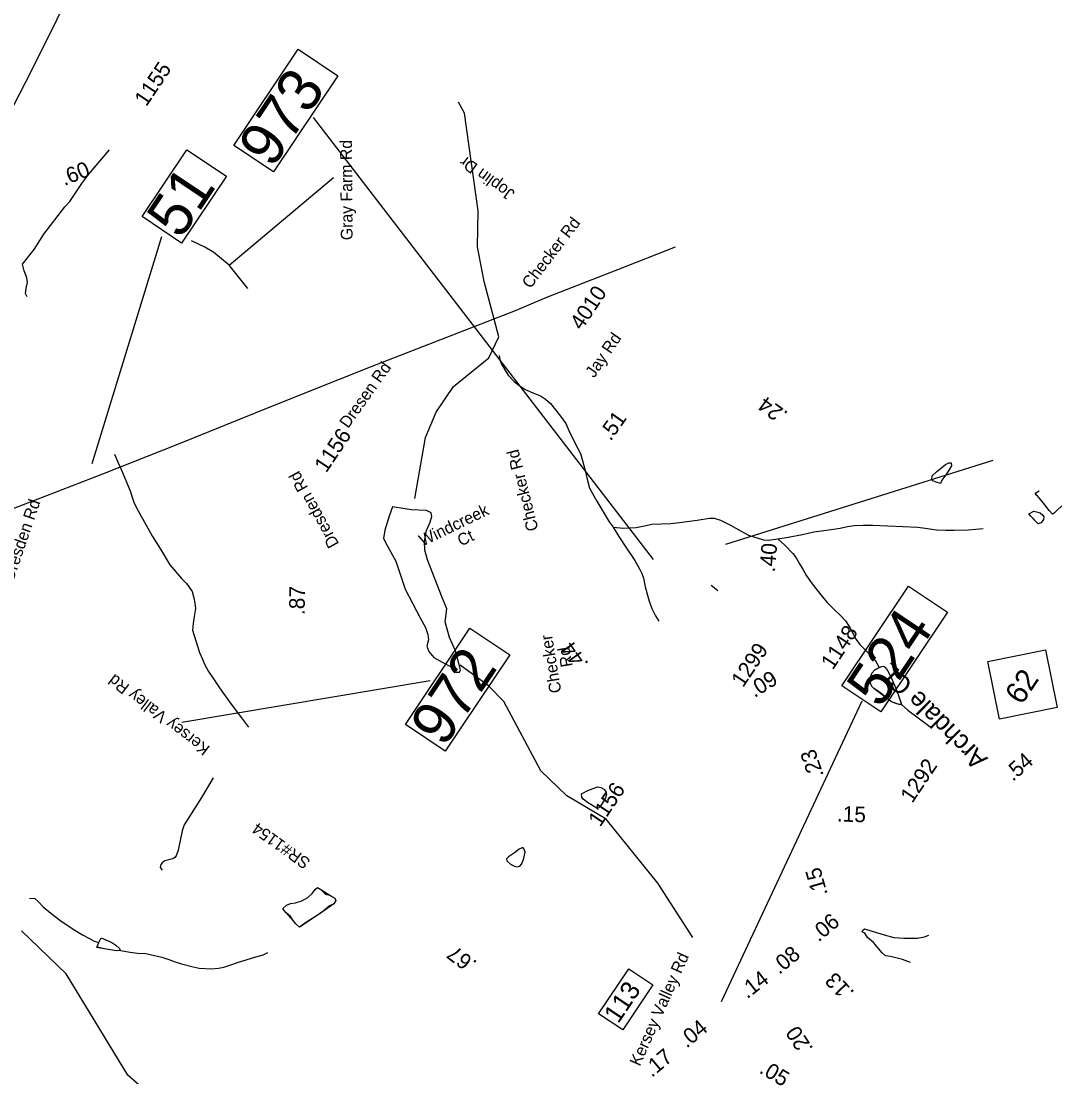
# Model space of a CAD drawing. Extents: x 1716282 to 1717158, y 799307 to 801078.
# Drawn here: x 1717037.3 to 1717158.4, y 800850 to 800972.8 of the extents above; entities that cross this region are included whole.
import ezdxf

# ---------------------------------------------------------------- set-up
doc = ezdxf.new("R2010")
doc.units = 0
for name, color, linetype in [('Exist Civil Demographics Community Label', 7, 'Continuous'), ('Exist Hydrographic Misc Water Feature', 7, 'Continuous'), ('Exist Hydrographic Pond Under 1500 Sq Ft', 7, 'Continuous'), ('Exist Road Non-System Type 51', 7, 'Continuous'), ('Exist Road Non-System Type 51 Label', 7, 'Continuous'), ('Exist Road Primary Interstate Interchange CELL', 7, 'Continuous'), ('Exist Road Primary NC Mileage Hundredths English Label', 7, 'Continuous'), ('Exist Road Primary NC Service Mileage Hundredths English Label', 7, 'Continuous'), ('Exist Road Primary NC Shield CELL', 7, 'Continuous'), ('Exist Road Primary NC Shield Number Label', 7, 'Continuous'), ('Exist Road Primary NC Structure Standard Bridge Number Label', 7, 'Continuous'), ('Exist Road Primary US Structure Standard Bridge Number Label', 7, 'Continuous'), ('Exist Road Secondary Mileage Hundredths English Label', 7, 'Continuous'), ('Exist Road Secondary Mileage Tenths English Label', 7, 'Continuous'), ('Exist Road Secondary Structure Standard Bridge Number Label', 7, 'Continuous'), ('Exist Road Secondary Type 51 Label', 7, 'Continuous'), ('Exist Road Secondary Type 51 Number Label', 7, 'Continuous'), ('Exist Utilities Electrical Transmission Line', 7, 'Continuous')]:
    doc.layers.add(name, color=color, linetype=linetype)

msp = doc.modelspace()

# ---------------------------------------------------------------- linework, layer by layer
at = {"layer": 'Exist Hydrographic Misc Water Feature'}
msp.add_line((1717136.7, 800898.41), (1717137.12, 800897.63), dxfattribs=at)
for points in [[(1717083.11, 800917.3), (1717084.34, 800924.37), (1717085.59, 800927.32), (1717087.62, 800930.32), (1717091.71, 800933.67), (1717092.88, 800936.09), (1717091.17, 800942.53), (1717090.4, 800946.57), (1717090.48, 800950.76), (1717088.89, 800962.1), (1717088.19, 800963.39)], [(1717092.92, 800933.93), (1717092.99, 800933.46), (1717093.14, 800933.01), (1717093.57, 800932.26), (1717093.98, 800931.63), (1717094.68, 800930.9), (1717095.23, 800930.46), (1717095.92, 800929.99), (1717096.65, 800929.66), (1717097.35, 800929.4), (1717097.73, 800929.24), (1717098.31, 800928.85), (1717098.88, 800928.35), (1717100.05, 800926.88), (1717100.68, 800926), (1717101.15, 800924.94), (1717102.06, 800923.09), (1717102.38, 800922.52), (1717102.83, 800920.87), (1717103.15, 800919.54), (1717103.41, 800918.48), (1717104.28, 800916.97), (1717105.73, 800914.57), (1717106.18, 800913.95)], [(1717048.17, 800922.46), (1717048.63, 800921.44), (1717049, 800920.59), (1717050.02, 800918.17), (1717050.26, 800917.45), (1717050.49, 800916.76), (1717050.95, 800915.84), (1717052.62, 800912.88), (1717053.53, 800911.38), (1717054.64, 800909.57), (1717055.98, 800907.98), (1717056.57, 800907.41), (1717056.88, 800906.98), (1717057.23, 800906.46), (1717057.43, 800905.73), (1717057.54, 800905.13), (1717057.62, 800904.51), (1717057.52, 800904.02), (1717057.44, 800903.58), (1717057.34, 800902.77), (1717057.26, 800901.98), (1717057.44, 800901.37), (1717058.08, 800899.38), (1717058.42, 800898.59), (1717058.67, 800898.03), (1717059.14, 800897.18), (1717059.71, 800896.31), (1717060.24, 800895.49), (1717060.73, 800894.77), (1717061.87, 800893.21), (1717062.94, 800891.78), (1717063.79, 800890.71)], [(1717144.26, 800919.03), (1717143.73, 800919.18), (1717143.36, 800919.36), (1717143.24, 800919.55), (1717143.29, 800919.94), (1717143.82, 800920.45), (1717144.2, 800920.75), (1717144.82, 800921.24), (1717145.23, 800921.43), (1717145.49, 800921.45), (1717145.52, 800921.08), (1717145.27, 800920.62), (1717144.86, 800920.06), (1717144.41, 800919.42), (1717144.32, 800919.23), (1717144.26, 800919.03)], [(1717144.26, 800919.03), (1717143.73, 800919.18), (1717143.36, 800919.36), (1717143.24, 800919.55), (1717143.29, 800919.94), (1717143.82, 800920.45), (1717144.82, 800921.24), (1717145.23, 800921.43), (1717145.49, 800921.45), (1717145.52, 800921.08), (1717145.27, 800920.62), (1717144.86, 800920.06), (1717144.41, 800919.42), (1717144.32, 800919.23), (1717144.26, 800919.03)], [(1717155.26, 800917.91), (1717155.74, 800918.18)], [(1717155.26, 800917.91), (1717155.74, 800918.18)], [(1717158.36, 800916.43), (1717157.82, 800915.95), (1717157.47, 800915.59), (1717157.28, 800915.47), (1717156.89, 800915.88), (1717156.39, 800916.54), (1717155.92, 800917.14), (1717155.42, 800917.69), (1717155.26, 800917.91)], [(1717158.36, 800916.43), (1717157.82, 800915.95), (1717157.47, 800915.59), (1717157.28, 800915.47), (1717156.89, 800915.88), (1717156.39, 800916.54), (1717155.92, 800917.14), (1717155.26, 800917.91)], [(1717154.54, 800915.52), (1717155.11, 800915.8), (1717155.43, 800915.75), (1717155.85, 800915.64), (1717156.15, 800915.36), (1717156.26, 800915.15), (1717156.21, 800914.83), (1717155.97, 800914.47), (1717155.6, 800914.34), (1717155.23, 800914.73), (1717154.76, 800915.23), (1717154.54, 800915.52)], [(1717154.54, 800915.52), (1717155.11, 800915.8), (1717155.43, 800915.75), (1717155.85, 800915.64), (1717156.15, 800915.36), (1717156.26, 800915.15), (1717156.21, 800914.83), (1717155.97, 800914.47), (1717155.6, 800914.34), (1717154.76, 800915.23), (1717154.54, 800915.52)], [(1717106.18, 800913.95), (1717107.37, 800913.84), (1717108.84, 800913.93), (1717109.82, 800914.13), (1717110.67, 800914.29), (1717111.75, 800914.33), (1717112.87, 800914.37), (1717113.89, 800914.48), (1717115.96, 800914.79), (1717117.38, 800915.01), (1717117.93, 800914.99), (1717118.66, 800914.77), (1717119.81, 800914.2), (1717121.05, 800913.49), (1717121.93, 800913.03), (1717123.67, 800912.5), (1717124.25, 800912.43), (1717125.35, 800912.59)], [(1717106.18, 800913.95), (1717106.85, 800912.86), (1717107.75, 800911.51), (1717108.71, 800910.08), (1717109.28, 800909.02), (1717109.52, 800908.55), (1717109.7, 800908.04), (1717109.89, 800907.03), (1717110.37, 800905.36), (1717110.69, 800904.51), (1717111.09, 800903.64), (1717111.5, 800903.01)], [(1717125.35, 800912.59), (1717126.54, 800912.79), (1717128.19, 800913.1), (1717129.52, 800913.4), (1717130.39, 800913.54), (1717131.53, 800913.67), (1717132.59, 800913.83), (1717133.44, 800914.05), (1717134.26, 800914.16), (1717135.25, 800914.18), (1717136.36, 800914.2), (1717141.6, 800913.96), (1717142.48, 800913.85), (1717143.77, 800913.64), (1717144.86, 800913.59), (1717145.84, 800913.59), (1717147.46, 800913.64), (1717148.35, 800913.71), (1717149.2, 800913.82)], [(1717125.35, 800912.59), (1717126.15, 800911.87), (1717127.08, 800910.91), (1717127.47, 800910.4), (1717127.87, 800909.71), (1717128.26, 800908.99), (1717128.66, 800908.29), (1717129.32, 800907.35), (1717130.49, 800905.88), (1717131.11, 800905.14), (1717131.9, 800904.39), (1717132.59, 800903.71), (1717133.2, 800903.05), (1717133.72, 800902.27), (1717134.15, 800901.41), (1717134.46, 800900.89), (1717134.88, 800900.32), (1717135.53, 800899.63), (1717136.25, 800898.93), (1717136.43, 800898.73), (1717136.7, 800898.41)], [(1717115.45, 800866.22), (1717111.38, 800872.53), (1717105.38, 800879.98), (1717100.78, 800882.69), (1717097.78, 800885.63), (1717093.48, 800893.68), (1717091.67, 800895.5), (1717088.37, 800897.91)], [(1717139.73, 800893.32), (1717139.45, 800893.33), (1717139.05, 800893.46), (1717138.56, 800893.62), (1717138.1, 800893.97), (1717137.52, 800894.51), (1717137.02, 800894.85), (1717136.51, 800895.2), (1717136.28, 800895.43), (1717136.05, 800895.9), (1717136.11, 800896.46), (1717136.26, 800896.99), (1717136.63, 800897.37), (1717137.06, 800897.6), (1717137.12, 800897.63)], [(1717139.73, 800893.32), (1717139.45, 800893.33), (1717138.56, 800893.62), (1717138.1, 800893.97), (1717136.51, 800895.2), (1717136.28, 800895.43), (1717136.05, 800895.9), (1717136.11, 800896.46), (1717136.26, 800896.99), (1717136.63, 800897.37), (1717137.12, 800897.63)], [(1717137.12, 800897.63), (1717137.41, 800897.75), (1717137.64, 800897.77), (1717137.92, 800897.57), (1717138.24, 800897), (1717138.64, 800896.2), (1717139.02, 800895.31), (1717139.34, 800894.5), (1717139.53, 800893.91), (1717139.66, 800893.47), (1717139.73, 800893.32)], [(1717137.12, 800897.63), (1717137.41, 800897.75), (1717137.64, 800897.77), (1717137.92, 800897.57), (1717138.24, 800897), (1717138.64, 800896.2), (1717139.02, 800895.31), (1717139.34, 800894.5), (1717139.53, 800893.91), (1717139.73, 800893.32)], [(1717139.73, 800893.32), (1717140.43, 800892.66), (1717142.84, 800890.88), (1717143.1, 800890.7)], [(1717067.76, 800869.59), (1717068.19, 800870), (1717068.67, 800870.19), (1717069.24, 800870.26), (1717069.97, 800870.5), (1717070.69, 800870.89), (1717071.17, 800871.33), (1717071.55, 800871.84), (1717071.79, 800872.04), (1717072.19, 800871.8), (1717072.55, 800871.45), (1717072.73, 800871.25), (1717073.25, 800871.14), (1717073.56, 800870.97), (1717073.8, 800870.8), (1717073.93, 800870.54), (1717073.71, 800870.16), (1717073.21, 800869.9), (1717072.62, 800869.39), (1717071.87, 800868.85), (1717071.12, 800868.38), (1717070.65, 800868.1), (1717070.12, 800867.73), (1717069.69, 800867.42), (1717069.29, 800867.8), (1717068.96, 800868.2), (1717068.65, 800868.67), (1717068.1, 800869.15), (1717067.91, 800869.38), (1717067.76, 800869.59)], [(1717067.76, 800869.59), (1717068.19, 800870), (1717068.67, 800870.19), (1717069.24, 800870.26), (1717069.97, 800870.5), (1717070.69, 800870.89), (1717071.17, 800871.33), (1717071.55, 800871.84), (1717071.79, 800872.04), (1717072.19, 800871.8), (1717073.56, 800870.97), (1717073.8, 800870.8), (1717073.93, 800870.54), (1717073.71, 800870.16), (1717071.87, 800868.85), (1717069.69, 800867.42), (1717069.29, 800867.8), (1717068.1, 800869.15), (1717067.91, 800869.38), (1717067.76, 800869.59)], [(1717038.31, 800870.8), (1717038.91, 800870.75), (1717039.32, 800870.43), (1717039.9, 800869.79), (1717040.79, 800869.04), (1717041.96, 800868.17), (1717043.4, 800867.19), (1717044.46, 800866.53), (1717045.2, 800866.13), (1717045.83, 800865.81), (1717046.38, 800865.64)], [(1717052.04, 800848.2), (1717049.74, 800850.22), (1717042.58, 800861.99), (1717037.38, 800867)], [(1717048.87, 800864.71), (1717048.4, 800864.69), (1717047.73, 800864.79), (1717047, 800864.9), (1717046.37, 800865.06), (1717046.13, 800865.08), (1717046.38, 800865.64)], [(1717048.87, 800864.71), (1717048.4, 800864.69), (1717047.73, 800864.79), (1717047, 800864.9), (1717046.13, 800865.08), (1717046.38, 800865.64)], [(1717046.38, 800865.64), (1717046.65, 800866.19), (1717047.18, 800865.94), (1717047.89, 800865.63), (1717048.36, 800865.35), (1717048.74, 800864.98), (1717048.87, 800864.71)], [(1717046.38, 800865.64), (1717046.65, 800866.19), (1717047.89, 800865.63), (1717048.36, 800865.35), (1717048.74, 800864.98), (1717048.87, 800864.71)], [(1717048.87, 800864.71), (1717050.01, 800864.53), (1717050.87, 800864.4), (1717051.84, 800864.37), (1717053.68, 800863.93), (1717054.49, 800863.68), (1717055.14, 800863.45), (1717055.99, 800863.15), (1717057.33, 800862.8), (1717058.03, 800862.64), (1717059.46, 800862.57), (1717060.28, 800862.65), (1717060.89, 800862.76), (1717061.73, 800863.06), (1717062.49, 800863.31), (1717064.64, 800863.99), (1717065.46, 800864.21), (1717066.03, 800864.48)]]:
    msp.add_lwpolyline(points, dxfattribs=at)
at = {"layer": 'Exist Hydrographic Pond Under 1500 Sq Ft'}
for points in [[(1717082.74, 800915.99), (1717080.5, 800916.33), (1717080.17, 800915.34), (1717079.62, 800913.61), (1717079.47, 800912.64), (1717079.91, 800911.83), (1717080.89, 800910.01), (1717082.01, 800906.75), (1717083.73, 800903.41), (1717084.37, 800902.28), (1717084.61, 800901.47), (1717084.71, 800900.84), (1717084.51, 800900.13), (1717084.75, 800899.51), (1717085.34, 800898.79), (1717086.28, 800898.25), (1717087.36, 800897.71), (1717087.88, 800897.09), (1717088.3, 800897.09), (1717088.44, 800897.37), (1717087.86, 800899.57), (1717087.13, 800901.13), (1717086.63, 800902.95), (1717086.84, 800904.45), (1717086.3, 800905.79), (1717084.57, 800910.16), (1717084.29, 800911.28), (1717084.25, 800912.33), (1717084.48, 800913.57), (1717084.9, 800914.55), (1717085.1, 800915.2), (1717085.02, 800915.63), (1717084.49, 800915.89), (1717082.74, 800915.99)], [(1717104.29, 800881.28), (1717103.19, 800881.94), (1717102.7, 800882.33), (1717102.53, 800882.56), (1717102.49, 800882.93), (1717103.25, 800883.34), (1717104.36, 800883.77), (1717104.75, 800883.66), (1717105.09, 800883.48), (1717105.34, 800883.2), (1717105.4, 800882.89), (1717105.28, 800882.47), (1717105.03, 800881.99), (1717104.71, 800881.49), (1717104.53, 800881.29), (1717104.29, 800881.28)], [(1717094.71, 800876.09), (1717094.01, 800875.61), (1717093.78, 800875.37), (1717093.82, 800875.16), (1717094.26, 800874.76), (1717094.71, 800874.51), (1717094.94, 800874.43), (1717095.32, 800874.52), (1717095.53, 800874.75), (1717095.74, 800875.3), (1717095.94, 800876.16), (1717095.84, 800876.52), (1717095.68, 800876.68), (1717095.26, 800876.49), (1717094.71, 800876.09)], [(1717140.77, 800863.31), (1717139.81, 800863.68), (1717138.45, 800864.02), (1717137.84, 800864.11), (1717137.46, 800864.44), (1717136.44, 800865.65), (1717135.77, 800866.24), (1717135.44, 800866.74), (1717135.14, 800866.87), (1717135.2, 800867.08), (1717135.4, 800867.22), (1717136.3, 800866.98), (1717137.7, 800866.54), (1717138.82, 800866.21), (1717140, 800866.13), (1717141.56, 800866.14), (1717142.38, 800866.3), (1717142.91, 800866.5)]]:
    msp.add_lwpolyline(points, dxfattribs=at)
at = {"layer": 'Exist Road Non-System Type 51'}
for p, q in [((1717061.53, 800944.43), (1717073.64, 800954.62)), ((1717063.68, 800941.73), (1717061.53, 800944.43))]:
    msp.add_line(p, q, dxfattribs=at)
for points in [[(1717038.04, 800940.76), (1717037.84, 800941.13), (1717037.91, 800941.7), (1717038.08, 800942.44), (1717037.98, 800942.97), (1717037.68, 800943.79), (1717037.48, 800944.54), (1717038.86, 800946.24), (1717039.99, 800948.05), (1717042.41, 800951.22), (1717042.99, 800951.84), (1717044.4, 800953.95), (1717045.15, 800954.97), (1717047.59, 800957.86)], [(1717061.53, 800944.43), (1717059.73, 800945.89), (1717058.71, 800946.53), (1717057.14, 800947.28)], [(1717117.58, 800907.22), (1717118.37, 800906.58)], [(1717059.66, 800884.81), (1717058.3, 800882.53), (1717057.1, 800880.63), (1717056.3, 800879.33), (1717056.05, 800878.65), (1717055.58, 800876.37), (1717055.36, 800875.72), (1717055.22, 800875.55), (1717054.99, 800875.38), (1717054.05, 800875.13), (1717053.72, 800874.93), (1717053.57, 800874.71), (1717053.49, 800874.37), (1717053.75, 800874.05)]]:
    msp.add_lwpolyline(points, dxfattribs=at)
at = {"layer": 'Exist Road Primary Interstate Interchange CELL'}
msp.add_lwpolyline([(1717104.48, 800857.35), (1717107.99, 800862.59), (1717110.8, 800860.71), (1717107.29, 800855.47)], close=True, dxfattribs=at)
at = {"layer": 'Exist Road Primary NC Shield CELL'}
msp.add_lwpolyline([(1717151.1, 800891.64), (1717149.77, 800898.34), (1717156.47, 800899.67), (1717157.8, 800892.97)], close=True, dxfattribs=at)
at = {"layer": 'Exist Road Primary NC Structure Standard Bridge Number Label'}
msp.add_line((1717118.78, 800858.77), (1717135.15, 800893.74), dxfattribs=at)
msp.add_lwpolyline([(1717132.79, 800895.51), (1717140.54, 800907.09), (1717145.06, 800904.07), (1717137.31, 800892.49)], close=True, dxfattribs=at)
at = {"layer": 'Exist Road Primary US Structure Standard Bridge Number Label'}
for p, q in [((1717110.88, 800910.19), (1717071.33, 800961.61)), ((1717119.28, 800911.98), (1717150.39, 800921.76))]:
    msp.add_line(p, q, dxfattribs=at)
msp.add_lwpolyline([(1717062.05, 800958.37), (1717069.54, 800969.57), (1717074.17, 800966.47), (1717066.67, 800955.27)], close=True, dxfattribs=at)
at = {"layer": 'Exist Road Secondary Structure Standard Bridge Number Label'}
for p, q in [((1717045.59, 800921.38), (1717053.69, 800947.77)), ((1717056.03, 800891.28), (1717084.89, 800896.14))]:
    msp.add_line(p, q, dxfattribs=at)
for points in [[(1717051.4, 800950.09), (1717056.59, 800957.85), (1717061.2, 800954.77), (1717056, 800947.01)], [(1717082.03, 800891.02), (1717089.52, 800902.22), (1717094.15, 800899.12), (1717086.66, 800887.92)]]:
    msp.add_lwpolyline(points, close=True, dxfattribs=at)
at = {"layer": 'Exist Utilities Electrical Transmission Line'}
for points in [[(1717048.36, 800990.05), (1717048.52, 800987.62), (1717044.45, 800979.06), (1717038.49, 800966.99), (1717035.76, 800961.65), (1717032.38, 800954.97), (1717028.55, 800947.16), (1717024.08, 800937.87), (1717020.93, 800931.21), (1717016.76, 800922.67)], [(1717113.38, 800946.53), (1717106.69, 800943.87), (1717098.42, 800940.66), (1717094.79, 800939.11), (1717087.49, 800936.29), (1717077.91, 800932.55), (1717070.7, 800929.7), (1717064.61, 800927.25), (1717055.5, 800923.57), (1717046.79, 800920.13), (1717040.78, 800917.8), (1717032.3, 800914.53), (1717020.79, 800909.99), (1717010.13, 800905.8), (1717008.63, 800906.48)]]:
    msp.add_lwpolyline(points, dxfattribs=at)

# ---------------------------------------------------------------- texts
at = {"layer": 'Exist Civil Demographics Community Label'}
msp.add_text('Archdale CL', height=2.175, rotation=135.2015, dxfattribs=at).set_placement((1717149.85, 800887.06))
at = {"layer": 'Exist Road Non-System Type 51 Label'}
for s, height, rotation, p in [('Jay Rd', 1.377, 55.5418, (1717103.97, 800931.24)), ('Dresen Rd', 1.377, 54.6676, (1717075.36, 800925.37)), ('Kersey Valley Rd', 1.3775, 65.9817, (1717109.28, 800851.17))]:
    msp.add_text(s, height=height, rotation=rotation, dxfattribs=at).set_placement(p)
at = {"layer": 'Exist Road Primary Interstate Interchange CELL'}
msp.add_text('113', height=2.175, rotation=56.2051, dxfattribs=at).set_placement((1717106.77, 800856.12))
at = {"layer": 'Exist Road Primary NC Mileage Hundredths English Label'}
for s, rotation, p in [('.54', 41.1366, (1717152.66, 800884.31)), ('.06', 40.0129, (1717130.08, 800865.64)), ('.08', 39.5315, (1717125.49, 800861.86)), ('.17', 40.0117, (1717110.68, 800849.89))]:
    msp.add_text(s, height=1.812, rotation=rotation, dxfattribs=at).set_placement(p)
at = {"layer": 'Exist Road Primary NC Service Mileage Hundredths English Label'}
for s, rotation, p in [('.14', 37.8811, (1717121.78, 800859.03)), ('.04', 39.7662, (1717114.74, 800853.29))]:
    msp.add_text(s, height=1.812, rotation=rotation, dxfattribs=at).set_placement(p)
at = {"layer": 'Exist Road Primary NC Shield Number Label'}
msp.add_text('62', height=2.537, rotation=56.2051, dxfattribs=at).set_placement((1717153.69, 800893.18))
at = {"layer": 'Exist Road Primary NC Structure Standard Bridge Number Label'}
msp.add_text('524', height=5.075, rotation=56.2051, dxfattribs=at).set_placement((1717137.26, 800892.74))
at = {"layer": 'Exist Road Primary US Structure Standard Bridge Number Label'}
msp.add_text('973', height=5.075, rotation=56.2051, dxfattribs=at).set_placement((1717066.54, 800955.58))
at = {"layer": 'Exist Road Secondary Mileage Hundredths English Label'}
for s, height, rotation, p in [('.60', 1.812, 21.8247, (1717042.36, 800953.64)), ('.24', 1.812, 143.5666, (1717126.62, 800927.27)), ('.40', 1.812, 85.3947, (1717124.99, 800908.67)), ('.87', 1.813, 89.2996, (1717070.3, 800903.73)), ('.09', 1.812, 31.7347, (1717122.62, 800894.07)), ('.23', 1.812, 109.1056, (1717130.7, 800885.1)), ('.15', 1.812, 358.0974, (1717132.18, 800879.73)), ('.15', 1.812, 105.8577, (1717131.15, 800871.28)), ('.67', 1.813, 142.9372, (1717090.46, 800863.38)), ('.20', 1.812, 123.5405, (1717129.51, 800853.32)), ('.05', 1.813, 328.8811, (1717123.06, 800850.55))]:
    msp.add_text(s, height=height, rotation=rotation, dxfattribs=at).set_placement(p)
at = {"layer": 'Exist Road Secondary Mileage Tenths English Label'}
for s, height, rotation, p in [('.51', 1.812, 54.499, (1717105.88, 800923.89)), ('.44', 1.812, 125.4196, (1717103.39, 800898.09)), ('.13', 1.813, 133.6735, (1717134.31, 800859.88))]:
    msp.add_text(s, height=height, rotation=rotation, dxfattribs=at).set_placement(p)
at = {"layer": 'Exist Road Secondary Structure Standard Bridge Number Label'}
for s, p in [('51', (1717055.87, 800947.32)), ('972', (1717086.52, 800888.23))]:
    msp.add_text(s, height=5.075, rotation=56.2051, dxfattribs=at).set_placement(p)
at = {"layer": 'Exist Road Secondary Type 51 Label'}
for s, height, rotation, p in [('Gray Farm Rd', 1.3775, 90.4665, (1717075.89, 800947.34)), ('Joplin Dr', 1.377, 144.0963, (1717094.85, 800952.97)), ('Checker Rd', 1.377, 52.6141, (1717096.55, 800941.62)), ('Checker Rd', 1.377, 104.1018, (1717097.5, 800913.68)), ('Dresden Rd', 1.377, 118.7678, (1717074.34, 800912)), ('Dresden Rd', 1.377, 71.123, (1717036.41, 800907.61)), ('Windcreek ', 1.377, 25.7252, (1717084.02, 800911.7)), ('Ct', 1.377, 25.7252, (1717088.47, 800911.7)), ('Checker', 1.377, 99.3081, (1717100.17, 800894.77)), (' Rd', 1.377, 99.3081, (1717101.55, 800897.29)), ('Kersey Valley Rd', 1.3775, 142.6388, (1717059.39, 800888.38)), ('SR#1154', 1.377, 144.3427, (1717071.08, 800875.2))]:
    msp.add_text(s, height=height, rotation=rotation, dxfattribs=at).set_placement(p)
at = {"layer": 'Exist Road Secondary Type 51 Number Label'}
for s, p in [('1155', (1717051.89, 800962.8)), ('4010', (1717102.52, 800936.77)), ('1156', (1717072.81, 800920.19)), ('1148', (1717131.72, 800897.27)), ('1299', (1717121.29, 800895.22)), ('1292', (1717140.96, 800881.76)), ('1156', (1717104.66, 800878.99))]:
    msp.add_text(s, height=1.812, rotation=56.2051, dxfattribs=at).set_placement(p)

doc.saveas('drawing.dxf')
